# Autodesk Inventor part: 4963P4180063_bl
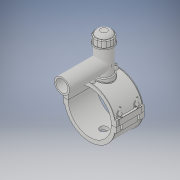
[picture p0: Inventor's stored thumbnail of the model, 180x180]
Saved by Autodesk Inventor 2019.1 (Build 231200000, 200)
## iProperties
Created: 2017-07
Part Number: 4963P4180063_bl
Material: Generic
Document SubType Name: Modeling
Designer: KIM
Density: 1 g/cm^3
Appearance: Default
Author: KIM
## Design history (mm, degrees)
derived "4963P4.ipt"
feature "Solid1::4963P4.ipt" dims "ScaleForDerivedMember" = 10
feature "Solid2::4963P4.ipt" dims "ScaleForDerivedMember" = 10
feature "Solid3::4963P4.ipt" dims "ScaleForDerivedMember" = 10
tag "TaggingFeature1"
body "Solid1"
body "Solid2"
body "Solid3"
other parameters: "d2" = 219 [user parameter], "d3" = 45 [user parameter], "d4" = 118 [user parameter], "d5" = 0 [user parameter], "d6" = 0.1 [user parameter], "d8" = 0 [user parameter], "d19" = 6 [user parameter], "d20" = 6 [user parameter], "d21" = 70.8 [user parameter], "d23" = 0 [user parameter], "d24" = 35.4 [user parameter], "d26" = 0 [user parameter], "d27" = 3 [user parameter], "d28" = 3 [user parameter], "d29" = 3 [user parameter], "d31" = 6 [user parameter], "d32" = 0 [user parameter], "d33" = 0 [user parameter], "d34" = 0.6 [user parameter], "d40" = 108.576 [user parameter], "d41" = 75.6 [user parameter], "d43" = 0 [user parameter], "d45" = 0 [user parameter], "d47" = 175.2 [user parameter], "d70" = 15 [user parameter], "d72" = 0 [user parameter], "d73" = 6 [user parameter], "d75" = 5 [user parameter], "d76" = 0 [user parameter], "d77" = 9 [user parameter], "d79" = 15 [user parameter], "d80" = 47.2 [user parameter], "d82" = 5 deg [user parameter], "d84" = 4 [user parameter], "d85" = 14 [user parameter], "d86" = 0 [user parameter], "d87" = 3 [user parameter], "d88" = 0 [user parameter], "d89" = 1 [user parameter], "d90" = 1 [user parameter], "d91" = 94.4 [user parameter], "d92" = 0 [user parameter], "d93" = 0.5 [user parameter], "d94" = 94.73684 [user parameter], "d96" = 212.976 [user parameter], "d97" = 2.36 [user parameter], "d98" = 0 [user parameter], "d102" = 1.8 [user parameter], "d120" = 140 deg [user parameter], "d121" = 24.228 [user parameter], "d122" = 20 deg [user parameter], "d123" = 417.6 [user parameter], "d124" = 125.28 [user parameter], "d126" = 0 [user parameter], "d143" = 185.4 [user parameter], "d145" = 22.15385 [user parameter], "d149" = 2.7 [user parameter], "d150" = 24.36923 [user parameter], "d153" = 118 [user parameter], "d154" = 0 [user parameter], "d156" = 104.4 [user parameter], "d157" = 160 deg [user parameter], "d159" = 5.76 [user parameter], "d161" = 2.7 [user parameter], "d162" = 70.8 [user parameter], "d163" = 0 [user parameter], "d167" = 18 [user parameter], "d168" = 101.85366 [user parameter], "d170" = 3.75 [user parameter], "d172" = 0 [user parameter], "d173" = 1 [user parameter], "d176" = 20 deg [user parameter], "d177" = 12.6 [user parameter], "d178" = 28.8 [user parameter], "d180" = 0 [user parameter], "d183" = 11.52 [user parameter], "d184" = 10.08 [user parameter], "d185" = 38.35 [user parameter], "d186" = 38.35 [user parameter], "d187" = 104.4 [user parameter], "d188" = 8.64 [user parameter], "d189" = 12.6 [user parameter], "d190" = 0 [user parameter], "d191" = 156.6 [user parameter], "d193" = 8 [user parameter], "d194" = 4.13 [user parameter], "d195" = 90 deg [user parameter], "d197" = 0 [user parameter], "d199" = 0 [user parameter], "d200" = 14.4 [user parameter], "d202" = 0 [user parameter], "d203" = 177 [user parameter], "d204" = 71.82 [user parameter], "d205" = 52.92 [user parameter], "d206" = 64.26 [user parameter], "d207" = 132.75 [user parameter], "d208" = 138.06 [user parameter], "d209" = 164.61 [user parameter], "d210" = 65.016 [user parameter], "d211" = 75.6 [user parameter], "d212" = 60.48 [user parameter], "d213" = 29.25 [user parameter], "d216" = 0 [user parameter], "d217" = 18 [user parameter], "d218" = 18 [user parameter], "d219" = 3.6 [user parameter], "d224" = 0 [user parameter], "d225" = 64 [user parameter], "d226" = 63 [user parameter], "d227" = 50.4 [user parameter], "d228" = 175 [user parameter], "d230" = 3.6 [user parameter], "B_" = 219 [user parameter], "L_" = 118 [user parameter], "d_t" = 6 [user parameter], "H_2" = 177 [user parameter], "H_1" = 64 [user parameter], "d_1" = 63 [user parameter], "H_" = 175 [user parameter], "d1" = 208.8 [user parameter]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
